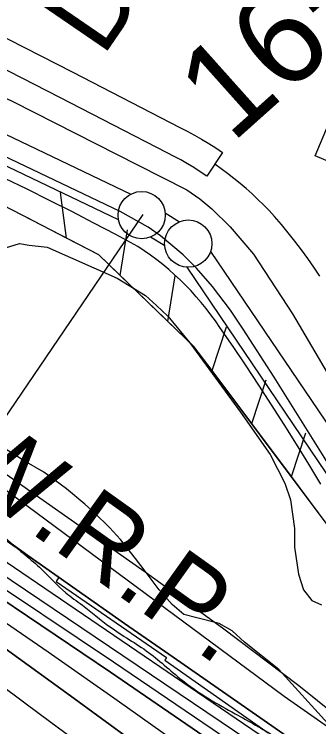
# Model space of a CAD drawing. Extents: x 3734862 to 3772949, y 391520 to 417239.
# Drawn here: x 3766031 to 3766353, y 397272 to 398025 of the extents above; entities that cross this region are included whole.
import ezdxf

# ---------------------------------------------------------------- set-up
doc = ezdxf.new("R2010")
doc.units = 0
for name, color, linetype in [('V-BLDG-OTLN', 7, 'Continuous'), ('V-FLOD-BASE', 7, 'Continuous'), ('V-LEVE-TOET', 7, 'Continuous'), ('V-RIVR-EDGE', 7, 'Continuous'), ('V-RIVR-RANG', 7, 'Continuous'), ('V-RIVR-RANG-IDEN', 7, 'Continuous'), ('V-ROAD-CNTR', 7, 'Continuous'), ('V-RRAP-FSHR', 7, 'Continuous'), ('V-RRAP-RVMT', 7, 'Continuous'), ('V-SITE-VEGE', 7, 'Continuous'), ('V-SURV-IDEN', 7, 'Continuous'), ('V-SURV-LINE', 7, 'Continuous'), ('V-TOPO-DPTH', 7, 'Continuous'), ('V-TOPO-MAJR', 7, 'Continuous'), ('V-TOPO-MINR', 7, 'Continuous'), ('V-TOPO-WATR', 7, 'Continuous'), ('V-TOPO-WATR-IDEN', 7, 'Continuous')]:
    doc.layers.add(name, color=color, linetype=linetype)

msp = doc.modelspace()

# ---------------------------------------------------------------- linework, layer by layer
at = {"layer": 'V-BLDG-OTLN'}
msp.add_lwpolyline([(3766404.17, 397917.59), (3766380.51, 397861.84), (3766348.85, 397875.28), (3766372.52, 397931.02)], close=True, dxfattribs=at)
at = {"layer": 'V-FLOD-BASE'}
msp.add_lwpolyline([(3766680.55, 397212.4), (3766658.39, 397229.33), (3766642.55, 397241.62), (3766613.21, 397266.22), (3766583.88, 397291.98), (3766518.75, 397351.71), (3766472.98, 397400.91), (3766426.04, 397451.87), (3766394.93, 397494.63), (3766358.52, 397556.73), (3766305.68, 397641.1), (3766272.81, 397692.07), (3766259.31, 397711.98), (3766240.52, 397737.17), (3766223.5, 397756.5), (3766209.42, 397770.56), (3766185.37, 397790.47), (3766172.46, 397799.83), (3766142.55, 397816.22), (3766019.39, 397875.31), (3765939.05, 397910.99)], dxfattribs=at)
at = {"layer": 'V-LEVE-TOET'}
for points in [[(3765782.02, 398053.35), (3765894.62, 397998.94), (3765919.54, 397983.68), (3765938.89, 397975.49), (3766029.8, 397932.2), (3766161.17, 397865.49), (3766213.37, 397839.16), (3766226.86, 397829.8), (3766239.77, 397819.26), (3766259.13, 397799.93), (3766283.78, 397771.23), (3766324.87, 397707.96), (3766405.31, 397571.45)], [(3766354.77, 397528.16), (3766342.08, 397549.27), (3766329.21, 397570.28), (3766316.14, 397591.16), (3766302.9, 397611.93), (3766289.47, 397632.59), (3766275.86, 397653.12), (3766262.07, 397673.53), (3766248.09, 397693.82), (3766243.46, 397700.57), (3766238.65, 397707.18), (3766233.66, 397713.67), (3766228.5, 397720.01), (3766223.16, 397726.21), (3766217.65, 397732.26), (3766211.98, 397738.16), (3766206.15, 397743.9), (3766200.16, 397749.48), (3766194.03, 397754.89), (3766187.75, 397760.13), (3766181.32, 397765.2), (3766174.76, 397770.09), (3766168.07, 397774.8), (3766161.25, 397779.32), (3766138.12, 397791.83), (3766114.88, 397804.13), (3766091.53, 397816.22), (3766068.07, 397828.09), (3766044.49, 397839.74), (3766020.82, 397851.18)]]:
    msp.add_lwpolyline(points, dxfattribs=at)
at = {"layer": 'V-RIVR-EDGE'}
msp.add_spline([(3755702.08, 404495.32), (3755757.18, 404470.77), (3755793.3, 404451.23), (3755852.47, 404424.41), (3755881.39, 404415.75), (3755906.23, 404404.38), (3755920.22, 404395.76), (3755948.67, 404379.41), (3755958.16, 404378.93), (3755969.01, 404378), (3755990.69, 404368.45), (3756022.75, 404350.29), (3756054.82, 404336.64), (3756079.66, 404323.02), (3756103.59, 404309.39), (3756144.23, 404288.04), (3756167.69, 404268.99), (3756188.91, 404253.57), (3756231.36, 404233.11), (3756271.56, 404217.19), (3756299.11, 404203.1), (3756403.01, 404163.51), (3756460.37, 404140.31), (3756508.69, 404114.87), (3756530.82, 404103.96), (3756588.18, 404078.04), (3756639.21, 404052.15), (3756694.29, 404019.45), (3756726.8, 403998.12), (3756735.82, 403989.06), (3756740.32, 403979.55), (3756740.3, 403973.22), (3756740.74, 403967.79), (3756747.5, 403960.54), (3756759.69, 403953.73), (3756786.34, 403941.46), (3756814.34, 403929.18), (3756864.47, 403904.64), (3756889.32, 403895.98), (3756899.72, 403897.32), (3756908.33, 403901.82), (3756919.18, 403901.34), (3756933.18, 403894.07), (3756945.83, 403892.68), (3756956.23, 403893.11), (3756962.12, 403897.16), (3756970.71, 403896.69), (3756978.39, 403894.41), (3756992.41, 403894.83), (3757002.82, 403897.51), (3757019.1, 403901.54), (3757027.7, 403901.52), (3757034.02, 403901.05), (3757036.27, 403896.53), (3757036.71, 403891.1), (3757038.5, 403883.41), (3757046.62, 403874.34), (3757060.62, 403866.17), (3757076.41, 403853.92), (3757104.39, 403831.25), (3757122.44, 403816.73), (3757145.47, 403804.47), (3757165.34, 403796.73), (3757181.6, 403787.2), (3757194.24, 403777.67), (3757213.65, 403765.41), (3757229.9, 403756.33), (3757251.58, 403745.88), (3757266.49, 403741.32), (3757283.2, 403734.49), (3757308.94, 403720.87), (3757360.42, 403694.06), (3757393.83, 403670.92), (3757429.96, 403657.26), (3757461.59, 403645.43), (3757505.4, 403628.14), (3757548.31, 403610.4), (3757591.66, 403587.23), (3757649.45, 403552.27), (3757711.75, 403512.78), (3757753.76, 403493.23), (3757766.86, 403487.78), (3757773.19, 403487.76), (3757785.86, 403494.06), (3757794.45, 403494.04), (3757803.49, 403489.49), (3757807.08, 403480.89), (3757810.64, 403456.02), (3757814.23, 403447.87), (3757826.42, 403436.99), (3757854.41, 403422.9), (3757930.26, 403373.88), (3757975.85, 403342.57), (3758005.19, 403323.5), (3758062.07, 403286.74), (3758092.31, 403263.6), (3758175.82, 403209.59), (3758234.51, 403169.2), (3758283.7, 403133.81), (3758328.84, 403103.41), (3758399.23, 403041.74), (3758421.79, 403023.15), (3758438.05, 403017.68), (3758463.83, 403017.62), (3758491.43, 403026.14), (3758504.53, 403022.04), (3758513.56, 403014.33), (3758513.99, 403006.19), (3758499.95, 402997.18), (3758498.12, 402989.95), (3758502.16, 402978.18), (3758510.73, 402969.57), (3758522.02, 402962.76), (3758545.05, 402948.69), (3758582.07, 402926.89), (3758650.23, 402878.79), (3758697.61, 402840.7), (3758721.52, 402820.29), (3758740.94, 402809.39), (3758782.02, 402784.87), (3758831.24, 402755.36), (3758902.12, 402711.78), (3758960.36, 402675.46), (3759018.58, 402634.62), (3759069.59, 402599.68), (3759134.59, 402553.4), (3759185.57, 402508.06), (3759223.48, 402478.12), (3759262.29, 402448.18), (3759321.41, 402402.37), (3759371.51, 402366.07), (3759431.54, 402323.42), (3759463.59, 402300.28), (3759488.86, 402281.68), (3759576.89, 402222.68), (3759626.99, 402186.84), (3759672.12, 402153.72), (3759778.21, 402087.44), (3759832.83, 402050.68), (3759873, 402019.38), (3759909.55, 401989.45), (3760050.81, 401883.75), (3760100.02, 401850.16), (3760145.61, 401819.31), (3760185.77, 401788.01), (3760211.95, 401766.69), (3760254.82, 401734.48), (3760285.51, 401709.08), (3760303.12, 401700.45), (3760325.25, 401691.35), (3760352.78, 401671.39), (3760391.14, 401641), (3760430.41, 401611.96), (3760461.55, 401590.18), (3760536.95, 401542.97), (3760582.99, 401510.76), (3760602.85, 401495.79), (3760629.02, 401477.18), (3760672.36, 401449.49), (3760711.19, 401426.79), (3760818.61, 401347.85), (3760872.33, 401310.64), (3760925.58, 401271.62), (3760948.6, 401251.67), (3761039.76, 401181.81), (3761107.02, 401135.52), (3761151.7, 401104.67), (3761172.93, 401093.31), (3761186.03, 401090.57), (3761199.15, 401092.79), (3761219.51, 401099.07), (3761228.11, 401099.5), (3761233.52, 401095.42), (3761236.67, 401087.73), (3761236.64, 401077.78), (3761228.47, 401063.78), (3761223.03, 401057.47), (3761223.01, 401049.33), (3761228.86, 401039.37), (3761242.39, 401026.67), (3761254.14, 401021.67), (3761266.79, 401018.47), (3761292.52, 401001.68), (3761317.34, 400980.37), (3761342.15, 400955.44), (3761463.07, 400853.4), (3761509.99, 400812.14), (3761550.15, 400777.68), (3761585.34, 400746.84), (3761681.47, 400674.26), (3761756.4, 400618.91), (3761817.77, 400572.19), (3761878.26, 400530.44), (3761996.49, 400436.55), (3762057.42, 400389.83), (3762104.8, 400352.63), (3762156.25, 400313.17), (3762204.54, 400277.33), (3762245.17, 400247.84), (3762291.65, 400210.19), (3762325.94, 400182.07), (3762356.18, 400159.84), (3762404.02, 400123.55), (3762432.9, 400101.32), (3762455.49, 400091.32), (3762473.53, 400075.9), (3762512.34, 400044.16), (3762551.6, 400012.41), (3762593.58, 399983.82), (3762620.21, 399963.4), (3762661.74, 399937.08), (3762686.57, 399919.83), (3762793.08, 399841.35), (3762834.61, 399812.76), (3762873.44, 399790.05), (3762923.1, 399758.28), (3762956.96, 399737.4), (3762984.05, 399721.5), (3763024.22, 399693.37), (3763075.23, 399657.52), (3763115.86, 399633.91), (3763172.75, 399601.21), (3763228.74, 399568.52), (3763285.17, 399533.57), (3763344.31, 399494.08), (3763398.47, 399455.06), (3763444.06, 399421.04), (3763484.68, 399391.09), (3763603.38, 399303.08), (3763654.82, 399261.81), (3763661.14, 399259.53), (3763667.01, 399254.54), (3763671.96, 399245.04), (3763696.33, 399224.18), (3763722.94, 399200.15), (3763745.5, 399180.2), (3763818.14, 399117.17), (3763841.61, 399099.47), (3763852.45, 399092.21), (3763858.76, 399084.06), (3763874.99, 399067.29), (3763898, 399045.98), (3763924.62, 399023.76), (3763949, 399007.87), (3763970.2, 398987.47), (3764004.03, 398952.57), (3764028.38, 398926.74), (3764056.8, 398899.54), (3764092.88, 398862.37), (3764130.77, 398826.11), (3764147.01, 398811.6), (3764152.86, 398799.83), (3764162.32, 398783.53), (3764173.58, 398768.58), (3764186.67, 398757.24), (3764206.08, 398746.34), (3764226.87, 398742.22), (3764246.29, 398733.58), (3764269.32, 398717.7), (3764284.2, 398703.19), (3764301.81, 398691.84), (3764323.02, 398678.23), (3764345.14, 398660.99), (3764412.35, 398596.62), (3764457.02, 398559.88), (3764502.6, 398522.69), (3764538.26, 398497.74), (3764566.26, 398486.36), (3764583.89, 398484.51), (3764604.25, 398486.27), (3764616.45, 398486.24), (3764626.39, 398481.69), (3764630.89, 398474.45), (3764636.29, 398461.32), (3764634.9, 398450.02), (3764631.72, 398441.44), (3764633.06, 398434.65), (3764636.21, 398430.12), (3764643.89, 398425.58), (3764661.06, 398421.47), (3764685.44, 398409.2), (3764715.22, 398382), (3764745.45, 398356.15), (3764793.31, 398328), (3764844.31, 398292.6), (3764885.83, 398258.14), (3764918.78, 398234.54), (3764992.82, 398187.79), (3765058.27, 398144.22), (3765088.07, 398128.32), (3765140.91, 398100.15), (3765168.89, 398079.74), (3765193.71, 398061.59), (3765246.12, 398042.02), (3765282.23, 398018.42), (3765309.74, 397989.41), (3765339.95, 397955.42), (3765361.15, 397933.67), (3765382.35, 397911.91), (3765434.69, 397867.92), (3765477.57, 397838.43), (3765508.73, 397823.88), (3765545.3, 397801.18), (3765575.54, 397778.05), (3765617.52, 397749.91), (3765653.64, 397726.31), (3765681.63, 397709.96), (3765727.23, 397684.53), (3765761.99, 397660.02), (3765771.94, 397659.55), (3765788.21, 397659.96), (3765793.64, 397658.14), (3765793.63, 397653.62), (3765785.47, 397648.66), (3765785.47, 397645.5), (3765790.86, 397632.82), (3765800.33, 397623.76), (3765814.78, 397612.87), (3765831.94, 397605.59), (3765847.31, 397603.29), (3765858.15, 397598.75), (3765865.82, 397593.3), (3765888.84, 397576.97), (3765908.7, 397561.54), (3765918.16, 397548.41), (3765919.5, 397542.07), (3765921.3, 397536.19), (3765926.71, 397533.46), (3765933.05, 397534.35), (3765940.73, 397533.43), (3765944.79, 397530.25), (3765956.97, 397519.37), (3765987.67, 397499.85), (3766024.67, 397468.11), (3766059.41, 397438.18), (3766085.13, 397413.25), (3766102.73, 397400.09), (3766131.61, 397377.42), (3766172.69, 397350.18), (3766210.59, 397318.89), (3766264.32, 397285.3), (3766306.76, 397260.78), (3766362.73, 397220.85), (3766381.12, 397208.5)], degree=3, dxfattribs=at)
at = {"layer": 'V-RIVR-RANG'}
msp.add_line((3766166.76, 397813.09), (3765749.46, 397200.27), dxfattribs=at)
at = {"layer": 'V-ROAD-CNTR'}
for points in [[(3765922.48, 398050.51), (3766092.78, 397963.66), (3766205.93, 397905.04), (3766213.53, 397901.19), (3766221.26, 397897.04), (3766228.89, 397892.71), (3766236.41, 397888.19), (3766243.82, 397883.51), (3766250.97, 397878.74), (3766234.34, 397853.77), (3766227.48, 397858.34), (3766220.67, 397862.65), (3766213.76, 397866.8), (3766206.75, 397870.78), (3766199.65, 397874.59), (3766192.24, 397878.35), (3766079.06, 397936.98), (3765931.69, 398012.14)], [(3766353.76, 397747.98), (3766347.48, 397757.4), (3766341.01, 397766.68), (3766334.35, 397775.83), (3766327.5, 397784.85), (3766320.48, 397793.72), (3766313.27, 397802.44), (3766305.88, 397811.02), (3766300.17, 397817.2), (3766294.31, 397823.24), (3766288.31, 397829.14), (3766282.18, 397834.9), (3766275.91, 397840.51), (3766269.5, 397845.97), (3766262.97, 397851.28), (3766256.32, 397856.43), (3766249.54, 397861.42), (3766242.65, 397866.26)]]:
    msp.add_lwpolyline(points, dxfattribs=at)
at = {"layer": 'V-RRAP-FSHR'}
for p, q in [((3766085.95, 397788.09), (3766079.46, 397836.48)), ((3766142.83, 397748.54), (3766150.4, 397796.78)), ((3766193.25, 397699.98), (3766200.82, 397748.23)), ((3766239.84, 397648.04), (3766255.05, 397694.45)), ((3766281.82, 397592.03), (3766297.03, 397638.43)), ((3766323.81, 397536.02), (3766339.02, 397582.42))]:
    msp.add_line(p, q, dxfattribs=at)
for points in [[(3763828.66, 399148.5), (3764283.79, 398756.79), (3764609.98, 398498.2), (3765271.96, 398085.75), (3765448.14, 397950), (3765966.29, 397562.89), (3766316.05, 397303.97), (3766451.05, 397209.41)], [(3766601.57, 397221.78), (3766586.06, 397233.5), (3766361.7, 397485.46), (3766220.77, 397673.48), (3766120.11, 397770.42), (3765775.08, 397948.91), (3765297.8, 398216.51), (3764998.22, 398390.52)], [(3766085.95, 397788.09), (3766043.15, 397810.23)], [(3766142.83, 397748.54), (3766120.11, 397770.42), (3766085.95, 397788.09)], [(3766193.25, 397699.98), (3766142.83, 397748.54)], [(3766239.84, 397648.04), (3766220.77, 397673.48), (3766193.25, 397699.98)], [(3766323.81, 397536.02), (3766281.82, 397592.03), (3766239.84, 397648.04)], [(3766366.23, 397480.37), (3766361.7, 397485.46), (3766323.81, 397536.02)]]:
    msp.add_lwpolyline(points, dxfattribs=at)
at = {"layer": 'V-RRAP-RVMT'}
for p, q in [((3765957.79, 397512.79), (3766077.69, 397429.75)), ((3766077.69, 397429.75), (3766075.05, 397425.27)), ((3766075.05, 397425.27), (3766191.83, 397344.73)), ((3766191.83, 397344.73), (3766189.84, 397342.07)), ((3766189.84, 397342.07), (3766299.34, 397265.03))]:
    msp.add_line(p, q, dxfattribs=at)
at = {"layer": 'V-SITE-VEGE'}
for p, q in [((3766021.46, 397777.79), (3766036.3, 397782.56)), ((3766036.3, 397782.56), (3766046.4, 397780.79)), ((3766046.4, 397780.79), (3766065.4, 397778.43)), ((3766065.4, 397778.43), (3766139.67, 397745.84)), ((3766139.67, 397745.84), (3766169.38, 397727.45)), ((3766169.38, 397727.45), (3766181.27, 397716.77)), ((3766181.27, 397716.77), (3766193.16, 397705.5)), ((3766193.16, 397705.5), (3766216.35, 397677.61)), ((3766216.35, 397677.61), (3766269.87, 397604.02)), ((3766269.87, 397604.02), (3766301.39, 397559.51)), ((3766041.27, 397552.73), (3766022.25, 397564.59)), ((3766301.39, 397559.51), (3766316.86, 397529.23)), ((3766062.06, 397540.87), (3766041.27, 397552.73)), ((3766085.84, 397523.07), (3766062.06, 397540.87)), ((3766316.86, 397529.23), (3766322.81, 397511.42)), ((3766105.45, 397507.05), (3766085.84, 397523.07)), ((3766322.81, 397511.42), (3766327, 397481.14)), ((3766115.56, 397497.56), (3766105.45, 397507.05)), ((3766131.61, 397482.14), (3766115.56, 397497.56)), ((3766142.9, 397469.67), (3766131.61, 397482.14)), ((3766327, 397481.14), (3766327.02, 397461.53)), ((3766158.96, 397449.5), (3766142.9, 397469.67)), ((3766327.02, 397461.53), (3766331.21, 397433.03)), ((3766170.26, 397434.66), (3766158.96, 397449.5)), ((3766183.93, 397416.26), (3766170.26, 397434.66)), ((3766331.21, 397433.03), (3766336.57, 397416.41)), ((3766197.61, 397400.84), (3766183.93, 397416.26)), ((3766336.57, 397416.41), (3766345.49, 397405.13)), ((3766210.09, 397390.16), (3766197.61, 397400.84)), ((3766345.49, 397405.13), (3766355.59, 397400.39)), ((3766223.75, 397386.61), (3766210.09, 397390.16)), ((3766247.52, 397380.69), (3766223.75, 397386.61)), ((3766261.18, 397372.98), (3766247.52, 397380.69)), ((3766274.26, 397361.12), (3766261.18, 397372.98)), ((3766310.51, 397332.05), (3766274.26, 397361.12)), ((3766362.24, 397275.09), (3766310.51, 397332.05))]:
    msp.add_line(p, q, dxfattribs=at)
at = {"layer": 'V-SURV-LINE'}
for points in [[(3765779.61, 398013.56), (3766153.92, 397834.59)], [(3766140.98, 397807.53), (3765766.66, 397986.5)], [(3766190.35, 397814.81), (3766205.51, 397805.54)], [(3766189.84, 397779.96), (3766174.68, 397789.23)], [(3766238.34, 397774.18), (3766437.6, 397479.74)], [(3766412.75, 397462.94), (3766213.49, 397757.37)]]:
    msp.add_lwpolyline(points, dxfattribs=at)
for centre in [(3766165.47, 397812.45), (3766214.72, 397782.32)]:
    msp.add_circle(centre, 25, dxfattribs=at)
at = {"layer": 'V-TOPO-DPTH'}
for points in [[(3766349.94, 397208.09), (3766278.64, 397256.63), (3765850.67, 397545.25), (3765820.62, 397565.41), (3765790.5, 397585.45), (3765760.27, 397605.34), (3765729.97, 397625.11), (3765655.75, 397673.28), (3765588.35, 397717.17), (3765521.05, 397761.21), (3765453.9, 397805.46), (3765386.83, 397849.85), (3765163.07, 397998.48), (3765140.92, 398013.32), (3765118.84, 398028.28), (3765096.89, 398043.4), (3765075.01, 398058.65), (3764529.77, 398441.72)], [(3766349.94, 397208.09), (3766278.64, 397256.63), (3765850.67, 397545.25), (3765820.62, 397565.41), (3765790.5, 397585.45), (3765760.27, 397605.34), (3765729.97, 397625.11), (3765655.75, 397673.28), (3765588.35, 397717.17), (3765521.05, 397761.21), (3765453.9, 397805.46), (3765386.83, 397849.85), (3765163.07, 397998.48), (3765140.92, 398013.32), (3765118.84, 398028.28), (3765096.89, 398043.4), (3765075.01, 398058.65), (3764529.77, 398441.72)], [(3765147.96, 398066.88), (3765278.68, 397977.46), (3765346.02, 397931.54), (3765413.43, 397885.74), (3765480.98, 397840.12), (3765548.6, 397794.63), (3765800.3, 397625.82), (3765804.92, 397622.69), (3765809.53, 397619.55), (3765814.12, 397616.38), (3765818.7, 397613.19), (3765851.08, 397590.47), (3765871.82, 397575.88), (3765892.53, 397561.26), (3765913.21, 397546.59), (3765933.87, 397531.89), (3765994.31, 397488.77), (3766045.24, 397452.59), (3766096.26, 397416.53), (3766147.42, 397380.67), (3766198.67, 397344.94), (3766394.91, 397208.68)], [(3766268.76, 397207.03), (3766212.35, 397247.54), (3766139.63, 397299.21), (3766066.57, 397350.39), (3765992.99, 397400.84), (3765919.08, 397450.79), (3765796.87, 397532.49), (3765783.76, 397541.16), (3765770.58, 397549.72), (3765757.31, 397558.13), (3765743.97, 397566.45), (3765468.19, 397736.19), (3765404.3, 397775.66), (3765340.51, 397815.28), (3765276.85, 397855.12), (3765213.28, 397895.11), (3765099.1, 397967.21), (3765092.73, 397971.31), (3765086.41, 397975.48), (3765080.15, 397979.76), (3765073.95, 397984.1), (3765006.27, 398032.33)], [(3766268.76, 397207.03), (3766212.35, 397247.54), (3766139.63, 397299.21), (3766066.57, 397350.39), (3765992.99, 397400.84), (3765919.08, 397450.79), (3765796.87, 397532.49), (3765783.76, 397541.16), (3765770.58, 397549.72), (3765757.31, 397558.13), (3765743.97, 397566.45), (3765468.19, 397736.19), (3765404.3, 397775.66), (3765340.51, 397815.28), (3765276.85, 397855.12), (3765213.28, 397895.11), (3765099.1, 397967.21), (3765092.73, 397971.31), (3765086.41, 397975.48), (3765080.15, 397979.76), (3765073.95, 397984.1), (3765006.27, 398032.33)], [(3765127.86, 397965.56), (3765737.58, 397590.83), (3765758.34, 397577.91), (3765779.01, 397564.85), (3765799.52, 397551.55), (3765819.95, 397538.11), (3766014.95, 397408.23), (3766132.38, 397329.12), (3766249.24, 397249.19), (3766308.74, 397207.56)], [(3765127.86, 397965.56), (3765737.58, 397590.83), (3765758.34, 397577.91), (3765779.01, 397564.85), (3765799.52, 397551.55), (3765819.95, 397538.11), (3766014.95, 397408.23), (3766132.38, 397329.12), (3766249.24, 397249.19), (3766308.74, 397207.56)], [(3765520.96, 397684.31), (3765569.07, 397654.16), (3765617.29, 397624.18), (3765665.57, 397594.3), (3765750.34, 397542.04), (3765756.27, 397538.35), (3765762.16, 397534.6), (3765768.02, 397530.8), (3765773.85, 397526.95), (3765828.17, 397490.63), (3765861, 397468.41), (3765893.67, 397445.93), (3765926.07, 397423.09), (3765958.3, 397399.99), (3766024.99, 397351.63), (3766090.36, 397304.07), (3766155.64, 397256.38), (3766220.76, 397208.48), (3766223.51, 397206.45)], [(3765520.96, 397684.31), (3765569.07, 397654.16), (3765617.29, 397624.18), (3765665.57, 397594.3), (3765750.34, 397542.04), (3765756.27, 397538.35), (3765762.16, 397534.6), (3765768.02, 397530.8), (3765773.85, 397526.95), (3765828.17, 397490.63), (3765861, 397468.41), (3765893.67, 397445.93), (3765926.07, 397423.09), (3765958.3, 397399.99), (3766024.99, 397351.63), (3766090.36, 397304.07), (3766155.64, 397256.38), (3766220.76, 397208.48), (3766223.51, 397206.45)]]:
    msp.add_lwpolyline(points, dxfattribs=at)
at = {"layer": 'V-TOPO-MAJR'}
msp.add_lwpolyline([(3766164.7, 397205.68), (3766164.18, 397206.06), (3766058.5, 397284.2), (3765796.09, 397479.4), (3765773.08, 397496.21), (3765749.89, 397512.74), (3765726.4, 397528.86), (3765702.73, 397544.72), (3765678.89, 397560.33), (3765655.01, 397575.89), (3765631.09, 397591.37), (3765607.13, 397606.8), (3765108.21, 397927.03), (3765089.81, 397939.04), (3765071.55, 397951.25), (3765053.48, 397963.75), (3765035.54, 397976.43), (3764752.63, 398179.95), (3764693.25, 398222.93)], dxfattribs=at)
at = {"layer": 'V-TOPO-MINR'}
for points in [[(3766349.94, 397208.09), (3766278.64, 397256.63), (3765850.67, 397545.25), (3765820.62, 397565.41), (3765790.5, 397585.45), (3765760.27, 397605.34), (3765729.97, 397625.11), (3765655.75, 397673.28), (3765588.35, 397717.17), (3765521.05, 397761.21), (3765453.9, 397805.46), (3765386.83, 397849.85), (3765163.07, 397998.48), (3765140.92, 398013.32), (3765118.84, 398028.28), (3765096.89, 398043.4), (3765075.01, 398058.65), (3764529.77, 398441.72)], [(3766460.76, 397209.53), (3766410.66, 397251.45), (3766331.81, 397314.78), (3766251.1, 397375.7), (3766169.14, 397435.03), (3765891.34, 397629.84), (3765863.96, 397648.96), (3765836.53, 397668), (3765809.03, 397686.94), (3765781.47, 397705.8), (3765710.36, 397754.27), (3765647.23, 397797.34), (3765584.12, 397840.43), (3765521.03, 397883.57), (3765457.96, 397926.73), (3765220.71, 398089.22), (3765197.96, 398104.67), (3765175.15, 398120.01), (3765152.21, 398135.17), (3765129.2, 398150.22), (3764731.19, 398408.46)], [(3766370.47, 397208.36), (3765852.77, 397560.8), (3765825.2, 397579.51), (3765797.61, 397598.18), (3765769.96, 397616.77), (3765742.28, 397635.32), (3765714.6, 397653.86), (3765686.95, 397672.44), (3765659.33, 397691.08), (3765631.75, 397709.77), (3765155.2, 398033.25), (3765143.46, 398041.26), (3765131.75, 398049.31), (3765120.08, 398057.41), (3765108.43, 398065.55), (3764966.67, 398165.13), (3764884.57, 398223.64), (3764803, 398282.88), (3764722.24, 398343.22)], [(3766329.37, 397207.82), (3766240.15, 397269.02), (3766135.69, 397339.68), (3765834.18, 397541.46), (3765809.29, 397557.98), (3765784.3, 397574.35), (3765759.19, 397590.52), (3765733.98, 397606.55), (3765421.76, 397803.33), (3765368.81, 397836.82), (3765315.92, 397870.42), (3765263.14, 397904.18), (3765210.43, 397938.04), (3765171.68, 397963.02), (3765138.56, 397984.72), (3765105.65, 398006.75), (3765073.08, 398029.26), (3765040.74, 398052.1), (3764815.59, 398213.54), (3764751.54, 398259.71), (3764687.64, 398306.09)], [(3766268.76, 397207.03), (3766212.35, 397247.54), (3766139.63, 397299.21), (3766066.57, 397350.39), (3765992.99, 397400.84), (3765919.08, 397450.79), (3765796.87, 397532.49), (3765783.76, 397541.16), (3765770.58, 397549.72), (3765757.31, 397558.13), (3765743.97, 397566.45), (3765468.19, 397736.19), (3765404.3, 397775.66), (3765340.51, 397815.28), (3765276.85, 397855.12), (3765213.28, 397895.11), (3765099.1, 397967.21), (3765092.73, 397971.31), (3765086.41, 397975.48), (3765080.15, 397979.76), (3765073.95, 397984.1), (3765006.27, 398032.33)], [(3766308.74, 397207.56), (3766249.24, 397249.19), (3766132.38, 397329.12), (3766014.95, 397408.23), (3765819.95, 397538.11), (3765799.52, 397551.55), (3765779.01, 397564.85), (3765758.34, 397577.91), (3765737.58, 397590.83), (3765127.86, 397965.56)], [(3766223.51, 397206.45), (3766220.76, 397208.48), (3766155.64, 397256.38), (3766090.36, 397304.07), (3766024.99, 397351.63), (3765958.3, 397399.99), (3765926.07, 397423.09), (3765893.67, 397445.93), (3765861, 397468.41), (3765828.17, 397490.63), (3765773.85, 397526.95), (3765768.02, 397530.8), (3765762.16, 397534.6), (3765756.27, 397538.35), (3765750.34, 397542.04), (3765665.57, 397594.3), (3765617.29, 397624.18), (3765569.07, 397654.16), (3765520.96, 397684.31)]]:
    msp.add_lwpolyline(points, dxfattribs=at)
at = {"layer": 'V-TOPO-WATR'}
msp.add_lwpolyline([(3766394.91, 397208.68), (3766198.67, 397344.94), (3766147.42, 397380.67), (3766096.26, 397416.53), (3766045.24, 397452.59), (3765994.31, 397488.77), (3765933.87, 397531.89), (3765913.21, 397546.59), (3765892.53, 397561.26), (3765871.82, 397575.88), (3765851.08, 397590.47), (3765818.7, 397613.19), (3765814.12, 397616.38), (3765809.53, 397619.55), (3765804.92, 397622.69), (3765800.3, 397625.82), (3765548.6, 397794.63), (3765480.98, 397840.12), (3765413.43, 397885.74), (3765346.02, 397931.54), (3765278.68, 397977.46), (3765147.96, 398066.88)], dxfattribs=at)

# ---------------------------------------------------------------- texts
at = {"layer": 'V-RIVR-RANG-IDEN'}
msp.add_text('D-040', height=83, rotation=55.60533, dxfattribs=at).set_placement((3766124.3, 397978.87))
at = {"layer": 'V-SURV-IDEN'}
msp.add_text('1656+89.1', height=100, rotation=41.7907, dxfattribs=at).set_placement((3766260.62, 397887.55))
at = {"layer": 'V-TOPO-WATR-IDEN'}
msp.add_text('L.W.R.P.', height=83, rotation=324.46272, dxfattribs=at).set_placement((3765884.49, 397593.25))

doc.saveas('drawing.dxf')
